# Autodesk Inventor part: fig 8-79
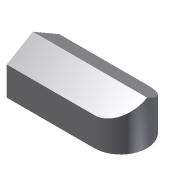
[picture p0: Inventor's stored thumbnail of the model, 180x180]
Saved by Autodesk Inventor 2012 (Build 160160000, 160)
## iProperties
Created: 2011-07
Part Number: fig 8-79
Material: Default
Document SubType Name: Modeling
Designer: CadCim
Density: 1 g/cm^3
Author: CadCim
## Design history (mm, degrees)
sketch "Sketch1"
  geometry: L1 (-16, 5)-(-16, -7); L2 (-16, -7)-(4, -7); L3 (4, 5)-(-16, 5); A1 r 6 centre (4, -1) between (4, -7) and (4, 5); 1 further point
  constraints: 6 end point, 2 point on circle, 2 tangent, 1 centre point, 1 parallel, 1 perpendicular, 1 vertical
extrude "Extrusion1" new body sketch "Sketch1" distance "d0" = 10; taper "d1" = 0 deg
sketch "Sketch2"
  geometry: L1 (-16, -1)-(10, -1); 1 further point
  constraints: 2 end point, 1 horizontal
feature "FaceDraft1" sketch "Sketch2" dims angle "d2" = 30 deg
body "Solid1"
